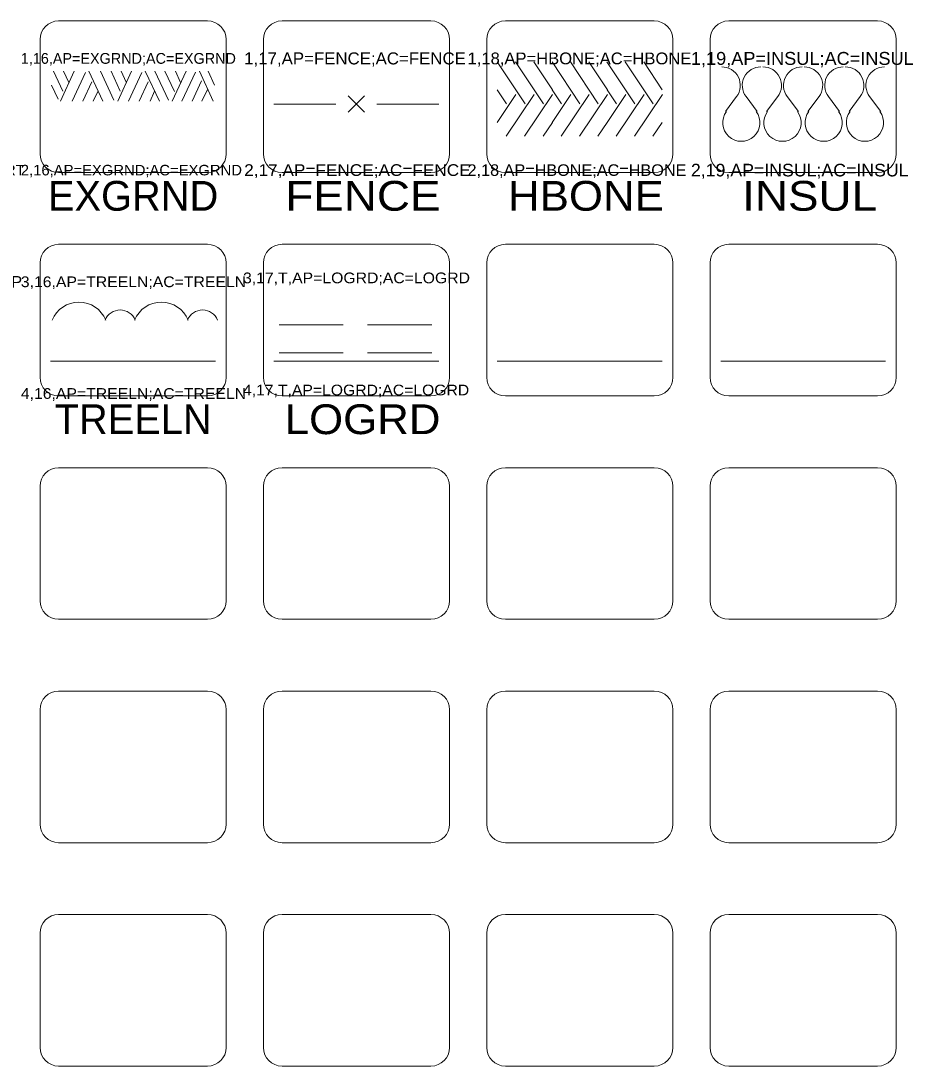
# Model space of a CAD drawing. Extents: x 95935 to 95946.4, y 95971.2 to 95974.7.
# Drawn here: x 95944.034 to 95946.431, y 95971.925 to 95974.732 of the extents above; entities that cross this region are included whole.
import ezdxf
from ezdxf.enums import TextEntityAlignment as Align

# ---------------------------------------------------------------- set-up
doc = ezdxf.new("R2010")
doc.units = 0
doc.header["$LTSCALE"] = 0.032
for name, color, linetype, lineweight in [('1', 7, 'Continuous', 13), ('25', 7, 'Continuous', 13), ('6', 7, 'Continuous', 13), ('63', 7, 'Continuous', 13)]:
    doc.layers.add(name, color=color, linetype=linetype, lineweight=lineweight)
doc.layers.add('20', color=7, linetype='Continuous')

msp = doc.modelspace()

# ---------------------------------------------------------------- linework, layer by layer
at = {"layer": '1'}
for p, q in [((95944.1357, 95974.7318), (95944.5357, 95974.7318)), ((95944.7357, 95974.7318), (95945.1357, 95974.7318)), ((95945.3357, 95974.7318), (95945.7357, 95974.7318)), ((95945.9357, 95974.7318), (95946.3357, 95974.7318)), ((95944.0857, 95974.3747), (95944.0857, 95974.6818)), ((95944.5857, 95974.6818), (95944.5857, 95974.3747)), ((95944.6857, 95974.3747), (95944.6857, 95974.6818)), ((95945.1857, 95974.6818), (95945.1857, 95974.3747)), ((95945.2857, 95974.3747), (95945.2857, 95974.6818)), ((95945.7857, 95974.6818), (95945.7857, 95974.3747)), ((95945.8857, 95974.3747), (95945.8857, 95974.6818)), ((95946.3857, 95974.6818), (95946.3857, 95974.3747)), ((95944.5357, 95974.3247), (95944.1357, 95974.3247)), ((95945.1357, 95974.3247), (95944.7357, 95974.3247)), ((95945.7357, 95974.3247), (95945.3357, 95974.3247)), ((95946.3357, 95974.3247), (95945.9357, 95974.3247)), ((95944.1357, 95974.1318), (95944.5357, 95974.1318)), ((95944.7357, 95974.1318), (95945.1357, 95974.1318)), ((95945.3357, 95974.1318), (95945.7357, 95974.1318)), ((95945.9357, 95974.1318), (95946.3357, 95974.1318)), ((95944.0857, 95973.7747), (95944.0857, 95974.0818)), ((95944.5857, 95974.0818), (95944.5857, 95973.7747)), ((95944.6857, 95973.7747), (95944.6857, 95974.0818)), ((95945.1857, 95974.0818), (95945.1857, 95973.7747)), ((95945.2857, 95973.7747), (95945.2857, 95974.0818)), ((95945.7857, 95974.0818), (95945.7857, 95973.7747)), ((95945.8857, 95973.7747), (95945.8857, 95974.0818)), ((95946.3857, 95974.0818), (95946.3857, 95973.7747)), ((95944.5357, 95973.7247), (95944.1357, 95973.7247)), ((95945.1357, 95973.7247), (95944.7357, 95973.7247)), ((95945.7357, 95973.7247), (95945.3357, 95973.7247)), ((95946.3357, 95973.7247), (95945.9357, 95973.7247)), ((95944.1357, 95973.5318), (95944.5357, 95973.5318)), ((95944.7357, 95973.5318), (95945.1357, 95973.5318)), ((95945.3357, 95973.5318), (95945.7357, 95973.5318)), ((95945.9357, 95973.5318), (95946.3357, 95973.5318)), ((95944.0857, 95973.1747), (95944.0857, 95973.4818)), ((95944.5857, 95973.4818), (95944.5857, 95973.1747)), ((95944.6857, 95973.1747), (95944.6857, 95973.4818)), ((95945.1857, 95973.4818), (95945.1857, 95973.1747)), ((95945.2857, 95973.1747), (95945.2857, 95973.4818)), ((95945.7857, 95973.4818), (95945.7857, 95973.1747)), ((95945.8857, 95973.1747), (95945.8857, 95973.4818)), ((95946.3857, 95973.4818), (95946.3857, 95973.1747)), ((95944.5357, 95973.1247), (95944.1357, 95973.1247)), ((95945.1357, 95973.1247), (95944.7357, 95973.1247)), ((95945.7357, 95973.1247), (95945.3357, 95973.1247)), ((95946.3357, 95973.1247), (95945.9357, 95973.1247)), ((95944.1357, 95972.9318), (95944.5357, 95972.9318)), ((95944.7357, 95972.9318), (95945.1357, 95972.9318)), ((95945.3357, 95972.9318), (95945.7357, 95972.9318)), ((95945.9357, 95972.9318), (95946.3357, 95972.9318)), ((95944.0857, 95972.5747), (95944.0857, 95972.8818)), ((95944.5857, 95972.8818), (95944.5857, 95972.5747)), ((95944.6857, 95972.5747), (95944.6857, 95972.8818)), ((95945.1857, 95972.8818), (95945.1857, 95972.5747)), ((95945.2857, 95972.5747), (95945.2857, 95972.8818)), ((95945.7857, 95972.8818), (95945.7857, 95972.5747)), ((95945.8857, 95972.5747), (95945.8857, 95972.8818)), ((95946.3857, 95972.8818), (95946.3857, 95972.5747)), ((95944.5357, 95972.5247), (95944.1357, 95972.5247)), ((95945.1357, 95972.5247), (95944.7357, 95972.5247)), ((95945.7357, 95972.5247), (95945.3357, 95972.5247)), ((95946.3357, 95972.5247), (95945.9357, 95972.5247)), ((95944.1357, 95972.3318), (95944.5357, 95972.3318)), ((95944.7357, 95972.3318), (95945.1357, 95972.3318)), ((95944.7357, 95972.3318), (95945.1357, 95972.3318)), ((95945.3357, 95972.3318), (95945.7357, 95972.3318)), ((95945.9357, 95972.3318), (95946.3357, 95972.3318)), ((95944.0857, 95971.9747), (95944.0857, 95972.2818)), ((95944.5857, 95972.2818), (95944.5857, 95971.9747)), ((95944.6857, 95971.9747), (95944.6857, 95972.2818)), ((95944.6857, 95971.9747), (95944.6857, 95972.2818)), ((95945.1857, 95972.2818), (95945.1857, 95971.9747)), ((95945.1857, 95972.2818), (95945.1857, 95971.9747)), ((95945.2857, 95971.9747), (95945.2857, 95972.2818)), ((95945.7857, 95972.2818), (95945.7857, 95971.9747)), ((95945.8857, 95971.9747), (95945.8857, 95972.2818)), ((95946.3857, 95972.2818), (95946.3857, 95971.9747)), ((95944.5357, 95971.9247), (95944.1357, 95971.9247)), ((95945.1357, 95971.9247), (95944.7357, 95971.9247)), ((95945.1357, 95971.9247), (95944.7357, 95971.9247)), ((95945.7357, 95971.9247), (95945.3357, 95971.9247)), ((95946.3357, 95971.9247), (95945.9357, 95971.9247))]:
    msp.add_line(p, q, dxfattribs=at)
for centre, start, end in [((95944.1357, 95974.6818), 90, 180), ((95944.5357, 95974.6818), 0, 90), ((95944.7357, 95974.6818), 90, 180), ((95945.1357, 95974.6818), 0, 90), ((95945.3357, 95974.6818), 90, 180), ((95945.7357, 95974.6818), 0, 90), ((95945.9357, 95974.6818), 90, 180), ((95946.3357, 95974.6818), 0, 90), ((95944.1357, 95974.3747), 180, 270), ((95944.5357, 95974.3747), 270, 0), ((95944.7357, 95974.3747), 180, 270), ((95945.1357, 95974.3747), 270, 0), ((95945.3357, 95974.3747), 180, 270), ((95945.7357, 95974.3747), 270, 0), ((95945.9357, 95974.3747), 180, 270), ((95946.3357, 95974.3747), 270, 0), ((95944.1357, 95974.0818), 90, 180), ((95944.5357, 95974.0818), 0, 90), ((95944.7357, 95974.0818), 90, 180), ((95945.1357, 95974.0818), 0, 90), ((95945.3357, 95974.0818), 90, 180), ((95945.7357, 95974.0818), 0, 90), ((95945.9357, 95974.0818), 90, 180), ((95946.3357, 95974.0818), 0, 90), ((95944.1357, 95973.7747), 180, 270), ((95944.5357, 95973.7747), 270, 0), ((95944.7357, 95973.7747), 180, 270), ((95945.1357, 95973.7747), 270, 0), ((95945.3357, 95973.7747), 180, 270), ((95945.7357, 95973.7747), 270, 0), ((95945.9357, 95973.7747), 180, 270), ((95946.3357, 95973.7747), 270, 0), ((95944.1357, 95973.4818), 90, 180), ((95944.5357, 95973.4818), 0, 90), ((95944.7357, 95973.4818), 90, 180), ((95945.1357, 95973.4818), 0, 90), ((95945.3357, 95973.4818), 90, 180), ((95945.7357, 95973.4818), 0, 90), ((95945.9357, 95973.4818), 90, 180), ((95946.3357, 95973.4818), 0, 90), ((95944.1357, 95973.1747), 180, 270), ((95944.5357, 95973.1747), 270, 0), ((95944.7357, 95973.1747), 180, 270), ((95945.1357, 95973.1747), 270, 0), ((95945.3357, 95973.1747), 180, 270), ((95945.7357, 95973.1747), 270, 0), ((95945.9357, 95973.1747), 180, 270), ((95946.3357, 95973.1747), 270, 0), ((95944.1357, 95972.8818), 90, 180), ((95944.5357, 95972.8818), 0, 90), ((95944.7357, 95972.8818), 90, 180), ((95945.1357, 95972.8818), 0, 90), ((95945.3357, 95972.8818), 90, 180), ((95945.7357, 95972.8818), 0, 90), ((95945.9357, 95972.8818), 90, 180), ((95946.3357, 95972.8818), 0, 90), ((95944.1357, 95972.5747), 180, 270), ((95944.5357, 95972.5747), 270, 0), ((95944.7357, 95972.5747), 180, 270), ((95945.1357, 95972.5747), 270, 0), ((95945.3357, 95972.5747), 180, 270), ((95945.7357, 95972.5747), 270, 0), ((95945.9357, 95972.5747), 180, 270), ((95946.3357, 95972.5747), 270, 0), ((95944.1357, 95972.2818), 90, 180), ((95944.5357, 95972.2818), 0, 90), ((95944.7357, 95972.2818), 90, 180), ((95944.7357, 95972.2818), 90, 180), ((95945.1357, 95972.2818), 0, 90), ((95945.1357, 95972.2818), 0, 90), ((95945.3357, 95972.2818), 90, 180), ((95945.7357, 95972.2818), 0, 90), ((95945.9357, 95972.2818), 90, 180), ((95946.3357, 95972.2818), 0, 90), ((95944.1357, 95971.9747), 180, 270), ((95944.5357, 95971.9747), 270, 0), ((95944.7357, 95971.9747), 180, 270), ((95944.7357, 95971.9747), 180, 270), ((95945.1357, 95971.9747), 270, 0), ((95945.1357, 95971.9747), 270, 0), ((95945.3357, 95971.9747), 180, 270), ((95945.7357, 95971.9747), 270, 0), ((95945.9357, 95971.9747), 180, 270), ((95946.3357, 95971.9747), 270, 0)]:
    msp.add_arc(centre, 0.05, start, end, dxfattribs=at)
at = {"layer": '25'}
for p, q in [((95944.5569, 95973.8178), (95944.1141, 95973.8178)), ((95945.1569, 95973.8178), (95944.7141, 95973.8178)), ((95945.7569, 95973.8178), (95945.3141, 95973.8178)), ((95946.3569, 95973.8178), (95945.9141, 95973.8178))]:
    msp.add_line(p, q, dxfattribs=at)
at = {"layer": '6'}
for p, q in [((95945.3135, 95974.6218), (95945.3885, 95974.5093)), ((95945.3627, 95974.6218), (95945.4377, 95974.5093)), ((95945.4121, 95974.6218), (95945.4621, 95974.5468)), ((95945.4611, 95974.6218), (95945.5361, 95974.5093)), ((95945.5103, 95974.6218), (95945.5853, 95974.5093)), ((95945.5597, 95974.6218), (95945.6097, 95974.5468)), ((95945.6087, 95974.6218), (95945.6837, 95974.5093)), ((95945.6579, 95974.6218), (95945.7329, 95974.5093)), ((95945.7073, 95974.6218), (95945.7573, 95974.5468)), ((95944.1467, 95974.5428), (95944.1215, 95974.5968)), ((95944.1405, 95974.5163), (95944.1778, 95974.5968)), ((95944.1627, 95974.566), (95944.1487, 95974.5968)), ((95944.172, 95974.5163), (95944.2078, 95974.593)), ((95944.2547, 95974.5163), (95944.2172, 95974.5968)), ((95944.284, 95974.5185), (95944.2477, 95974.5968)), ((95944.301, 95974.5435), (95944.2765, 95974.5968)), ((95944.2944, 95974.5163), (95944.3317, 95974.5968)), ((95944.3167, 95974.567), (95944.3032, 95974.5968)), ((95944.3235, 95974.5163), (95944.359, 95974.5928)), ((95944.4062, 95974.5163), (95944.3685, 95974.5968)), ((95944.4306, 95974.5188), (95944.3943, 95974.5968)), ((95944.4465, 95974.542), (95944.4213, 95974.5968)), ((95944.4407, 95974.5163), (95944.478, 95974.597)), ((95944.4632, 95974.5663), (95944.4492, 95974.5968)), ((95944.4669, 95974.5163), (95944.5029, 95974.5943)), ((95944.5509, 95974.5163), (95944.5137, 95974.5968)), ((95944.5541, 95974.5593), (95944.5369, 95974.5968)), ((95944.1347, 95974.5213), (95944.1169, 95974.5593)), ((95944.2005, 95974.5163), (95944.2248, 95974.5685)), ((95944.3521, 95974.5163), (95944.3761, 95974.5685)), ((95944.4942, 95974.5163), (95944.5192, 95974.571)), ((95944.2287, 95974.5163), (95944.2415, 95974.544)), ((95944.3812, 95974.5163), (95944.3935, 95974.5433)), ((95944.5206, 95974.5163), (95944.5351, 95974.548)), ((95944.9135, 95974.4864), (95944.9575, 95974.5304)), ((95944.9575, 95974.4864), (95944.9135, 95974.5304)), ((95945.3637, 95974.5343), (95945.3137, 95974.4593)), ((95945.3139, 95974.5468), (95945.3389, 95974.5093)), ((95945.4131, 95974.5343), (95945.3381, 95974.4218)), ((95945.4623, 95974.5343), (95945.3873, 95974.4218)), ((95945.5113, 95974.5343), (95945.4613, 95974.4593)), ((95945.4615, 95974.5468), (95945.4865, 95974.5093)), ((95945.5607, 95974.5343), (95945.4857, 95974.4218)), ((95945.6099, 95974.5343), (95945.5349, 95974.4218)), ((95945.6589, 95974.5343), (95945.6089, 95974.4593)), ((95945.6091, 95974.5468), (95945.6341, 95974.5093)), ((95945.7083, 95974.5343), (95945.6333, 95974.4218)), ((95945.7575, 95974.5343), (95945.6825, 95974.4218)), ((95945.9268, 95974.4884), (95945.9568, 95974.5284)), ((95946.0121, 95974.4884), (95945.9821, 95974.5284)), ((95946.0375, 95974.4884), (95946.0675, 95974.5284)), ((95946.1228, 95974.4884), (95946.0928, 95974.5284)), ((95946.1482, 95974.4884), (95946.1782, 95974.5284)), ((95946.2335, 95974.4884), (95946.2035, 95974.5284)), ((95946.2589, 95974.4884), (95946.2889, 95974.5284)), ((95946.3442, 95974.4884), (95946.3142, 95974.5284)), ((95944.7141, 95974.5084), (95944.8801, 95974.5084)), ((95944.9908, 95974.5084), (95945.1569, 95974.5084)), ((95945.4619, 95974.4593), (95945.4369, 95974.4218)), ((95945.6095, 95974.4593), (95945.5845, 95974.4218)), ((95945.7571, 95974.4593), (95945.7321, 95974.4218)), ((95944.7278, 95973.9155), (95944.9004, 95973.9155)), ((95944.9652, 95973.9155), (95945.1378, 95973.9155)), ((95944.7278, 95973.8407), (95944.9004, 95973.8407)), ((95944.9652, 95973.8407), (95945.1378, 95973.8407))]:
    msp.add_line(p, q, dxfattribs=at)
for centre, radius, start, end in [((95945.9168, 95974.5584), 0.05, 323.1301, 90), ((95946.0221, 95974.5584), 0.05, 90, 216.8699), ((95946.0275, 95974.5584), 0.05, 323.1301, 90), ((95946.1328, 95974.5584), 0.05, 90, 216.8699), ((95946.1382, 95974.5584), 0.05, 323.1301, 90), ((95946.2435, 95974.5584), 0.05, 90, 216.8699), ((95946.2489, 95974.5584), 0.05, 323.1301, 90), ((95946.3542, 95974.5584), 0.05, 90, 216.8699), ((95945.9695, 95974.4584), 0.05, 143.1301, 36.8699), ((95946.0801, 95974.4584), 0.05, 143.1301, 36.8699), ((95946.1908, 95974.4584), 0.05, 143.1301, 36.8699), ((95946.3016, 95974.4584), 0.05, 143.1301, 36.8699), ((95944.1902, 95973.8985), 0.0779, 22.6224, 157.3788), ((95944.4116, 95973.8985), 0.0779, 22.6224, 157.3788), ((95944.301, 95973.9116), 0.0438, 22.6224, 157.3788), ((95944.5223, 95973.9116), 0.0438, 22.6224, 157.3788)]:
    msp.add_arc(centre, radius, start, end, dxfattribs=at)

# ---------------------------------------------------------------- texts
at = {"layer": '20'}
for s, p in [('EXGRND', (95944.3357, 95974.222)), ('TREELN', (95944.3359, 95973.622))]:
    msp.add_text(s, height=0.08, dxfattribs=at).set_placement(p, align=Align.CENTER)
for s, width, p in [(' FENCE', 1.15, (95944.9358, 95974.222)), (' HBONE', 1.1, (95945.5358, 95974.222)), (' INSUL', 1.15, (95946.1359, 95974.222)), (' LOGRD', 1.1, (95944.9358, 95973.622))]:
    msp.add_text(s, height=0.08, dxfattribs=dict(at, width=width)).set_placement(p, align=Align.CENTER)
at = {"layer": '63'}
msp.add_text('1,16,AP=EXGRND;AC=EXGRND', height=0.0289, dxfattribs=at).set_placement((95944.0341, 95974.6166))
for s, height, width, p in [('1,17,AP=FENCE;AC=FENCE', 0.0322, 1.05, (95944.6341, 95974.615)), ('1,18,AP=HBONE;AC=HBONE', 0.0317, 1.05, (95945.2341, 95974.6152)), ('1,19,AP=INSUL;AC=INSUL', 0.0347, 1.05, (95945.8341, 95974.6137)), ('2,15,AP=CONCRT;AC=CONCRT', 0.0278, 1.1, (95943.4341, 95974.3172)), ('2,16,AP=EXGRND;AC=EXGRND', 0.0283, 1.05, (95944.0341, 95974.3169)), ('2,17,AP=FENCE;AC=FENCE', 0.0314, 1.1, (95944.6341, 95974.3154)), ('2,18,AP=HBONE;AC=HBONE', 0.031, 1.05, (95945.2341, 95974.3156)), ('2,19,AP=INSUL;AC=INSUL', 0.0339, 1.05, (95945.8341, 95974.3141)), ('3,17,T,AP=LOGRD;AC=LOGRD', 0.0288, 1.1, (95944.6309, 95974.0272)), ('3,15,AP=TOPUP;AC=TOPUP', 0.0309, 1.1, (95943.4341, 95974.0156)), ('3,16,AP=TREELN;AC=TREELN', 0.0288, 1.1, (95944.0341, 95974.0167)), ('4,16,AP=TREELN;AC=TREELN', 0.0288, 1.1, (95944.0341, 95973.7167)), ('4,17,T,AP=LOGRD;AC=LOGRD', 0.0287, 1.1, (95944.6309, 95973.7261))]:
    msp.add_text(s, height=height, dxfattribs=dict(at, width=width)).set_placement(p)

doc.saveas('drawing.dxf')
